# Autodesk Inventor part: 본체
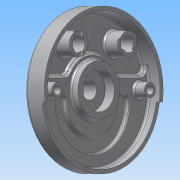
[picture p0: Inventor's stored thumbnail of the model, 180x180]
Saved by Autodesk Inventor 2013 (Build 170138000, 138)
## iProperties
Created: 2015-06
Part Number: 본체
Material: 알루미늄 6061
Document SubType Name: Modeling
Designer: Administrator
Density: 2.40731 g/cm^3
Mass: 949.174 g
Surface Area: 1033.28 cm^2
Volume: 394.288 cm^3
Author: Administrator
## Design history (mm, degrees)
sketch "스케치1"
  geometry: C1 r 95 at (0, 0); 1 further point
  constraints: 1 centre point, 1 coincident
  dimensions: "d0" = 190 diameter of C1
extrude "돌출1" new body sketch "스케치1" distance "d1" = 32; taper "d2" = 0 deg
sketch "스케치2"
  geometry: L1 (-40, 52)-(40, 52); C1 r 95 at (0, 0) reference; C2 r 10 at (-40, 52); C3 r 10 at (40, 52); A1 r 74 centre (0, 0) between (74, 0) and (-74, 0); 1 further point
  constraints: 3 centre point, 3 coincident, 2 end point, 2 horizontal alignment, 2 point on circle, 1 horizontal, 1 midpoint, 1 vertical alignment
  dimensions: "d3" = 148 diameter of A1; "d4" = 52 vertical distance of A1.start L1.end; "d5" = 80 distance of L1.end L1.start; "d6" = 20 diameter of C2; "d7" = 20 diameter of C3
extrude "돌출2" cut sketch "스케치2" distance "d8" = 32; taper "d9" = 0 deg
hole "구멍1" sketch "스케치2" diameter "d10" = 11; stored, may be unused: countersink angle "d14" = 90 deg, drill point angle "d16" = 118 deg; dims "d11" = 6, "d12" = 18, "d13" = 11, "d15" = 8
sketch "스케치4"
  geometry: C1 r 5.5 at (-74, 0) reference; C2 r 5.5 at (74, 0) reference; C3 r 10 at (40, 52) reference; C4 r 10 at (-40, 52) reference; C5 r 9 at (-74, 0); C6 r 9 at (74, 0); C7 r 15 at (40, 52); C8 r 15 at (-40, 52)
  constraints: 4 centre point, 4 coincident, 1 equal radius
  dimensions: "d17" = 30 diameter of C8; "d19" = 30 diameter of C7; "d20" = 18 diameter of C6
sketch "스케치5"
  geometry: C1 r 10 at (40, 52) reference; C2 r 10 at (-40, 52) reference; C3 r 95 at (0, 0) reference; C4 r 90 at (0, 0); C5 r 9 at (-74, 0) reference; C6 r 9 at (74, 0) reference
  constraints: 1 centre point, 1 coincident
  dimensions: "d21" = 180 diameter of C4
extrude "돌출3" cut sketch "스케치5" distance "d22" = 25; taper "d23" = 0 deg
extrude "돌출4" join sketch "스케치4" stored distance "d24" = 25; taper "d25" = 0 deg
sketch "스케치6"
  geometry: L1 (-90, 0)-(90, 0); L2 (-75.657, 16)-(-45.033, 16); L3 (45.033, 16)-(75.657, 16); C1 r 9 at (74, 0) reference; C2 r 9 at (-74, 0) reference; C3 r 90 at (0, 0) reference; C4 r 15 at (40, 52) reference; C5 r 15 at (-40, 52) reference; C6 r 9 at (74, 0) reference; C7 r 9 at (-74, 0) reference; C8 r 90 at (0, 0) reference; A1 r 90 centre (0, 0) between (88.566, 16) and (-88.566, 16) reference; A2 r 42 centre (0, 0) between (36.373, 21) and (-36.373, 21); A3 r 10 centre (45.033, 26) between (36.373, 21) and (45.033, 16); A4 r 10 centre (-45.033, 26) between (-45.033, 16) and (-36.373, 21); A5 r 90 centre (0, 0) between (85.114, 29.25) and (-85.114, 29.25); A6 r 10 centre (-75.657, 26) between (-85.114, 29.25) and (-75.657, 16); A7 r 10 centre (75.657, 26) between (75.657, 16) and (85.114, 29.25); 2 further points
  constraints: 20 point on circle, 8 tangent, 6 centre point, 6 end point, 4 point on line, 3 horizontal, 2 coincident, 2 equal radius
  dimensions: "d33" = 10 radius of A3; "d34" = 10 radius of A6
  node "투영된 루프1"
sketch "스케치7"
  geometry: C1 r 95 at (0, 0) reference; C2 r 26 at (0, 0)
  constraints: 1 centre point, 1 coincident
  dimensions: "d28" = 52 diameter of C2
extrude "돌출5" join sketch "스케치7" distance "d29" = 12; taper "d30" = -15 deg
extrude "돌출6" join sketch "스케치6" distance "d35" = 7; taper "d36" = 0 deg
sketch "스케치8"
  geometry: C1 r 35 at (0, 0); A1 r 90 centre (0, 0) between (-85.114, 29.25) and (85.114, 29.25) reference
  constraints: 1 centre point, 1 coincident
  dimensions: "d37" = 70 diameter of C1
extrude "돌출7" join sketch "스케치8" distance "d39" = 10; taper "d40" = -10 deg
sketch "스케치9"
  geometry: C1 r 33.237 at (0, 0) reference; 1 further point
  constraints: 1 coincident
hole "구멍2" sketch "스케치9" at (0, 0) diameter "d41" = 23; stored, may be unused: countersink angle "d45" = 90 deg, drill point angle "d47" = 118 deg; dims "d42" = 6, "d43" = 50, "d44" = 15, "d46" = 8
sketch "스케치10"
  geometry: L1 (0, -90)-(0, 106.968); L2 (-45.033, 16)-(-75.657, 16) reference; L3 (-37.391, -19.13)-(37.391, -19.13); A1 r 90 centre (0, 0) between (-85.114, 29.25) and (85.114, 29.25) reference; A2 r 9 centre (50, -14) between (58.999, -14.133) and (41, -14); A3 r 9 centre (-50, -14) between (-41, -14) and (-59, -14); A4 r 41 centre (0, -14) between (-41, -14) and (41, -14); A5 r 59 centre (0, -14) between (-59, -14) and (59, -14); A6 r 42 centre (0, 0) between (37.391, -19.13) and (-37.391, -19.13); 2 further points
  constraints: 14 point on circle, 5 centre point, 4 end point, 2 coincident, 2 horizontal alignment, 2 tangent, 2 vertical alignment, 1 parallel
  dimensions: "d58" = 18 diameter of A2; "d59" = 18 diameter of A3; "d60" = 41 radius of A4; "d62" = 84 diameter of A6; "d63" = 59 radius of A5; "d99" = 14 vertical distance of A2.centre A1.centre; "d102" = 18 distance of A3.start A3.end
extrude "돌출8" cut sketch "스케치10" distance "d64" = 7; taper "d65" = 0 deg
sketch "스케치11"
  geometry: L1 (-6, -20.288)-(6, -20.288); L2 (6, -20.288)-(6, 20.288); L3 (6, 20.288)-(-6, 20.288); L4 (-6, 20.288)-(-6, -20.288); L5 (-6, -20.288)-(6, 20.288); L6 (6, -20.288)-(-6, 20.288); L7 (50.338, -6)-(109.662, -6); L8 (109.662, -6)-(109.662, 6); L9 (109.662, 6)-(50.338, 6); L10 (50.338, 6)-(50.338, -6); L11 (50.338, -6)-(109.662, 6); L12 (109.662, -6)-(50.338, 6); C1 r 15 at (0, 0) reference; C2 r 10 at (80, 0) reference; 1 further point
  constraints: 24 end point, 4 midpoint, 4 parallel, 2 horizontal, 2 perpendicular
  dimensions: "d66" = 12 distance of L2.end L3.end; "d68" = 12 distance of L7.end L8.end
extrude "돌출9" cut sketch "스케치11" distance "d69" = 3; taper "d70" = 0 deg
sketch "스케치12"
  geometry: L1 (0, 0)-(-94.075, -13.221); L2 (0, 0)-(94.075, -13.221); L3 (-95, 0)-(95, 0); L4 (68.819, 58)-(69.662, 58) reference; L5 (69.662, 58)-(69.662, 56.984) reference; C1 r 11.5 at (0, 0) reference; C2 r 95 at (0, 0) reference; A1 r 95 centre (0, 0) between (-94.075, -13.221) and (94.075, -13.221) reference; A2 r 90 centre (0, 0) between (68.819, 58) and (69.662, 56.984) reference
  constraints: 6 end point, 4 point on circle
  dimensions: "d71" = 190 distance of L3.start L3.end; "d72" = 8 deg angle of L2 L3; "d73" = 8 deg angle of L1 L3
extrude "돌출10" cut sketch "스케치12" distance "d74" = 5; taper "d75" = 0 deg
fillet "모깎기1" dims "d76" = 5
sketch "스케치13"
  geometry: C1 r 90 at (0, 0) reference; C2 r 74 at (0, 0)
  constraints: 1 centre point, 1 coincident, 1 other
  dimensions: "d77" = 148 diameter of C2
feature "엠보싱1" sketch "스케치13" dims "d78" = 0.5, "d79" = 0
fillet "모깎기2" dims "d80" = 0.3
chamfer "모따기1" distance "d81" = 1; stored, may be unused: second distance "d82" = 2, angle "d83" = 45 deg
fillet "모깎기3" dims "d84" = 3
fillet "모깎기4" dims "d86" = 3
fillet "모깎기5" dims "d87" = 3
fillet "모깎기6" dims "d88" = 3
fillet "모깎기7" dims "d89" = 3
chamfer "모따기2" distance "d90" = 1; stored, may be unused: second distance "d91" = 2, angle "d92" = 45 deg
fillet "모깎기8" dims "d96" = 1
fillet "모깎기9" dims "d97" = 3
node "솔리드1"
node "투영된 루프2"
other parameters: "d26" = 84, "d32" = 16, "d56" = 82, "d57" = 118
